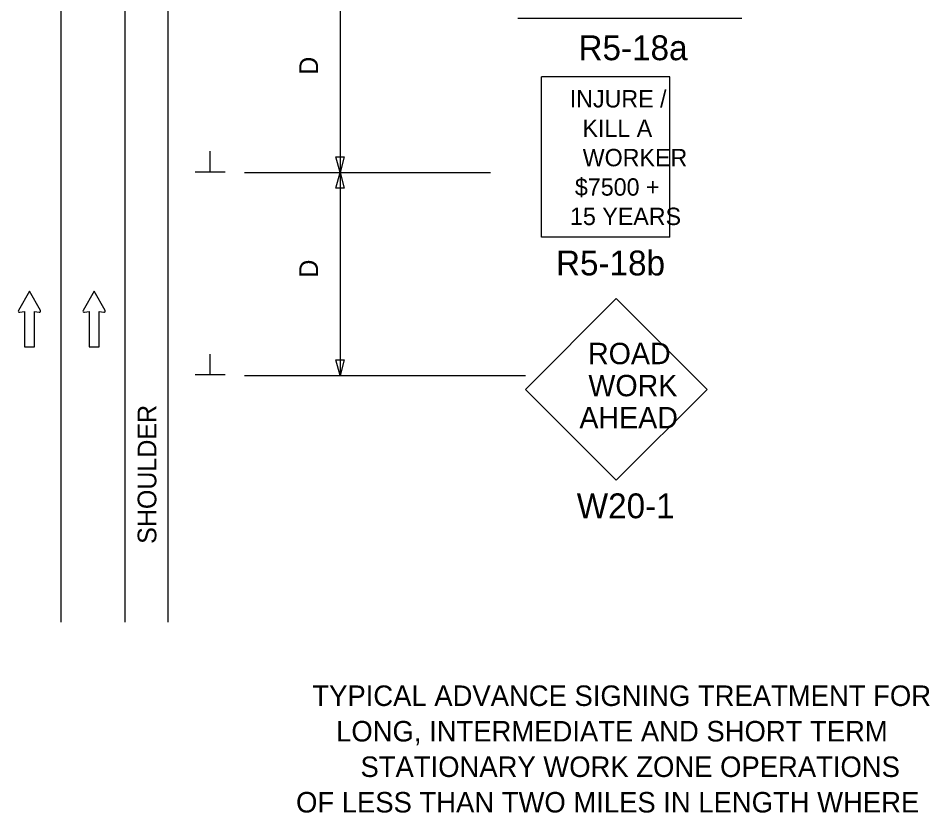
# Model space of a CAD drawing. Extents: x 19017 to 20754, y 4888 to 6104.
# Drawn here: x 19347 to 19688, y 5189.7 to 5487.1 of the extents above; entities that cross this region are included whole.
import ezdxf

# ---------------------------------------------------------------- set-up
doc = ezdxf.new("R2010")
doc.units = 0
for name, color, linetype in [('BORDER', 7, 'Continuous'), ('BORDER_SIGNAL_WO', 7, 'Continuous'), ('MT_SCRATCH_LEVEL_E', 7, 'Continuous'), ('PAVT_EDGE_EX', 7, 'Continuous'), ('TRAFFIC_SIGNS_PR', 7, 'Continuous'), ('TYPICAL_TEXT_DIMEN_PR', 7, 'Continuous')]:
    doc.layers.add(name, color=color, linetype=linetype)

msp = doc.modelspace()

# ---------------------------------------------------------------- linework, layer by layer
at = {"layer": 'BORDER'}
msp.add_line((19567.417, 5194.208), (19567.417, 5194.208), dxfattribs=at)
msp.add_line((19567.417, 5194.208), (19567.417, 5194.208), dxfattribs=at)
msp.add_line((19567.417, 5194.208), (19567.417, 5194.208), dxfattribs=at)
at = {"layer": 'MT_SCRATCH_LEVEL_E'}
for p, q in [((19351.148, 5384.986), (19347.037, 5377.745)), ((19351.148, 5384.986), (19347.037, 5377.745)), ((19355.295, 5377.745), (19351.148, 5384.986)), ((19355.295, 5377.745), (19351.148, 5384.986)), ((19375.362, 5384.986), (19371.251, 5377.745)), ((19375.362, 5384.986), (19371.251, 5377.745)), ((19379.509, 5377.745), (19375.362, 5384.986)), ((19379.509, 5377.745), (19375.362, 5384.986)), ((19347.519, 5377.061), (19349.296, 5377.377)), ((19347.519, 5377.061), (19349.296, 5377.377)), ((19349.296, 5377.377), (19349.296, 5364.119)), ((19349.296, 5377.377), (19349.296, 5364.119)), ((19353.038, 5364.119), (19353.038, 5377.377)), ((19353.038, 5377.377), (19354.816, 5377.061)), ((19353.038, 5364.119), (19353.038, 5377.377)), ((19353.038, 5377.377), (19354.816, 5377.061)), ((19371.733, 5377.061), (19373.51, 5377.377)), ((19371.733, 5377.061), (19373.51, 5377.377)), ((19373.51, 5377.377), (19373.51, 5364.119)), ((19373.51, 5377.377), (19373.51, 5364.119)), ((19377.252, 5364.119), (19377.252, 5377.377)), ((19377.252, 5377.377), (19379.03, 5377.061)), ((19377.252, 5364.119), (19377.252, 5377.377)), ((19377.252, 5377.377), (19379.03, 5377.061)), ((19349.296, 5364.119), (19353.038, 5364.119)), ((19349.296, 5364.119), (19353.038, 5364.119)), ((19373.51, 5364.119), (19377.252, 5364.119)), ((19373.51, 5364.119), (19377.252, 5364.119))]:
    msp.add_line(p, q, dxfattribs=at)
for centre, start, end in [((19347.445, 5377.521), 150.42484, 279.96381), ((19347.445, 5377.521), 150.42484, 279.96381), ((19354.885, 5377.522), 260.03619, 29.77312), ((19354.885, 5377.522), 260.03619, 29.77312), ((19371.659, 5377.521), 150.42484, 279.96381), ((19371.659, 5377.521), 150.42484, 279.96381), ((19379.099, 5377.522), 260.03619, 29.77312), ((19379.099, 5377.522), 260.03619, 29.77312)]:
    msp.add_arc(centre, 0.463, start, end, dxfattribs=at)
at = {"layer": 'PAVT_EDGE_EX'}
for p, q in [((19386.917, 6104.026), (19386.917, 5261.047)), ((19402.917, 6104.026), (19402.917, 5261.047)), ((19362.917, 6014.455), (19362.917, 5261.047))]:
    msp.add_line(p, q, dxfattribs=at)
for points in [[(19362.917, 5414.455), (19362.917, 5389.455)], [(19362.917, 5314.455), (19362.917, 5289.455)]]:
    msp.add_lwpolyline(points, dxfattribs=at)
at = {"layer": 'TRAFFIC_SIGNS_PR'}
for p, q in [((19533.859, 5487.084), (19616.251, 5487.084)), ((19616.251, 5487.084), (19617.705, 5487.084)), ((19542.711, 5405.134), (19542.711, 5465.134)), ((19590.711, 5465.134), (19542.711, 5465.134)), ((19590.711, 5405.134), (19590.711, 5465.134)), ((19590.711, 5405.134), (19542.711, 5405.134)), ((19570.73, 5382.134), (19536.789, 5348.193)), ((19604.671, 5348.193), (19570.73, 5382.134)), ((19536.789, 5348.193), (19570.73, 5314.252)), ((19570.73, 5314.252), (19604.671, 5348.193))]:
    msp.add_line(p, q, dxfattribs=at)
at = {"layer": 'TYPICAL_TEXT_DIMEN_PR'}
for p, q in [((19467.405, 5581.162), (19467.405, 5353.414)), ((19418.761, 5429.493), (19418.761, 5437.278)), ((19467.389, 5429.339), (19465.818, 5435.201)), ((19465.818, 5435.201), (19467.389, 5435.201)), ((19467.389, 5435.201), (19468.96, 5435.201)), ((19468.96, 5435.201), (19467.389, 5429.339)), ((19418.761, 5429.493), (19413.136, 5429.493)), ((19424.386, 5429.493), (19418.761, 5429.493)), ((19431.588, 5429.331), (19523.722, 5429.331)), ((19465.815, 5423.484), (19467.386, 5429.346)), ((19467.386, 5429.346), (19468.957, 5423.484)), ((19467.386, 5423.484), (19465.815, 5423.484)), ((19468.957, 5423.484), (19467.386, 5423.484)), ((19418.761, 5353.576), (19418.761, 5361.361)), ((19467.389, 5353.422), (19465.818, 5359.284)), ((19465.818, 5359.284), (19467.389, 5359.284)), ((19467.389, 5359.284), (19468.96, 5359.284)), ((19468.96, 5359.284), (19467.389, 5353.422)), ((19418.761, 5353.576), (19413.136, 5353.576)), ((19424.386, 5353.576), (19418.761, 5353.576)), ((19431.588, 5353.414), (19536.722, 5353.414)), ((19431.588, 5353.414), (19523.722, 5353.414))]:
    msp.add_line(p, q, dxfattribs=at)

# ---------------------------------------------------------------- texts
at = {"layer": 'BORDER_SIGNAL_WO'}
for s, p in [('TYPICAL ADVANCE SIGNING TREATMENT FOR', (19457.026, 5229.706)), ('LONG, INTERMEDIATE AND SHORT TERM ', (19465.916, 5216.418)), ('STATIONARY WORK ZONE OPERATIONS', (19475.032, 5203.131)), ('OF LESS THAN TWO MILES IN LENGTH WHERE ', (19450.917, 5189.843))]:
    msp.add_text(s, height=7.67305, dxfattribs=at).set_placement(p)
at = {"layer": 'TRAFFIC_SIGNS_PR'}
for s, height, p in [('R5-18a', 9.3, (19556.59, 5471.372)), ('INJURE /', 6.5, (19553.317, 5453.681)), ('KILL A', 6.5, (19558.067, 5442.681)), ('WORKER', 6.5, (19558.162, 5431.681)), ('$7500 +', 6.5, (19555.254, 5420.682)), ('15 YEARS', 6.5, (19553.417, 5409.682)), ('R5-18b', 9.3, (19548.181, 5390.834)), ('ROAD', 8, (19560.157, 5357.612)), ('WORK', 8, (19560.293, 5345.612)), ('AHEAD', 8, (19556.931, 5333.612)), ('W20-1', 9.3, (19555.942, 5299.953))]:
    msp.add_text(s, height=height, dxfattribs=at).set_placement(p)
at = {"layer": 'TYPICAL_TEXT_DIMEN_PR'}
for s, p in [('D', (19459.152, 5465.91)), ('D', (19459.152, 5389.993)), ('SHOULDER', (19398.66, 5290.377))]:
    msp.add_text(s, height=7, rotation=90, dxfattribs=at).set_placement(p)

doc.saveas('drawing.dxf')
